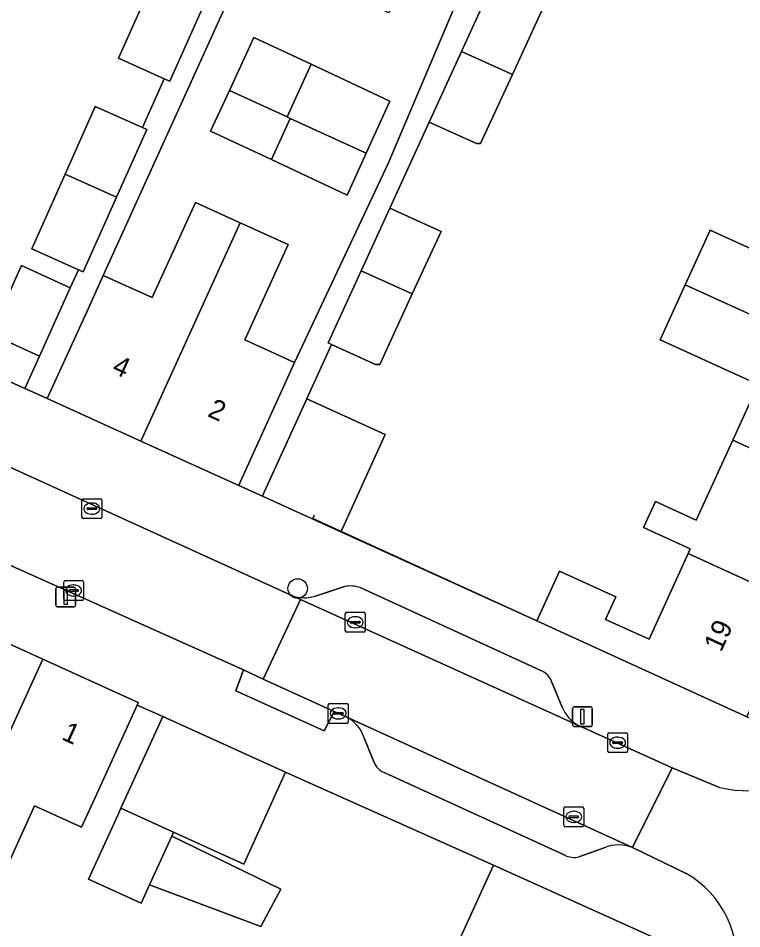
# Model space of a CAD drawing. Extents: x 161838 to 162344, y 381620 to 382160.
# Drawn here: x 162108.87 to 162145.23, y 381710.53 to 381756.3 of the extents above; entities that cross this region are included whole.
import ezdxf

# ---------------------------------------------------------------- set-up
doc = ezdxf.new("R2010")
doc.units = 0
for name, color, linetype in [('IMGEO_Boom', 7, 'Continuous'), ('IMGEO_Erf', 7, 'Continuous'), ('IMGEO_Kolk', 7, 'Continuous'), ('IMGEO_Lichtmast', 7, 'Continuous'), ('IMGEO_Muur', 7, 'Continuous'), ('IMGEO_Pand', 7, 'Continuous'), ('IMGEO_Pand_nummerreeks', 7, 'Continuous'), ('IMGEO_Parkeervlak_open', 7, 'Continuous'), ('IMGEO_Rijbaan_lokaal_open', 7, 'Continuous'), ('IMGEO_Voetpad_open', 7, 'Continuous')]:
    doc.layers.add(name, color=color, linetype=linetype)

msp = doc.modelspace()

# ---------------------------------------------------------------- linework, layer by layer
at = {"layer": 'IMGEO_Boom'}
msp.add_circle((162122.912, 381727.637), 0.489, dxfattribs=at)
at = {"layer": 'IMGEO_Erf'}
for points in [[(162094.462, 381744.361), (162109.199, 381737.693), (162109.937, 381739.317), (162107.478, 381740.434), (162109.029, 381743.87), (162111.487, 381742.753), (162111.903, 381743.659), (162109.549, 381744.71), (162111.227, 381748.467), (162112.742, 381751.86), (162115.113, 381750.802), (162116.21, 381753.261), (162113.902, 381754.292), (162115.58, 381758.049), (162117.095, 381761.442), (162119.401, 381760.413), (162120.584, 381763.066), (162118.111, 381764.199), (162119.612, 381767.472), (162119.687, 381767.636), (162117.321, 381768.718), (162119.551, 381773.591), (162104.902, 381780.293)], [(162135.187, 381756.685), (162133.706, 381753.472), (162132.105, 381750), (162131.895, 381750), (162129.52, 381751.082), (162127.539, 381746.757), (162130.115, 381745.582), (162128.667, 381742.44), (162127.033, 381738.897), (162126.823, 381738.897), (162124.609, 381739.906), (162123.489, 381737.446), (162123.366, 381737.176), (162127.307, 381735.385), (162125.559, 381731.538), (162125.24, 381730.836), (162125.078, 381730.479), (162134.933, 381726.013), (162136.075, 381728.515), (162138.903, 381727.225), (162138.383, 381726.082), (162140.569, 381725.085), (162142.533, 381729.392), (162142.638, 381729.623), (162140.29, 381730.694), (162140.887, 381732.002), (162142.937, 381731.066), (162144.775, 381735.096), (162146.048, 381737.887), (162141.124, 381740.133), (162142.389, 381742.908), (162143.638, 381745.647), (162148.57, 381743.398)], [(162131, 381709.87), (162132.746, 381713.736), (162123.45, 381717.876), (162122.299, 381718.4), (162120.198, 381713.786), (162116.674, 381715.392), (162116.58, 381715.187), (162122.071, 381712.514), (162121.067, 381710.646), (162115.466, 381712.742), (162115.047, 381711.821), (162112.406, 381713.024), (162113.885, 381716.271), (162114.033, 381716.595), (162116.134, 381721.209), (162114.846, 381721.774), (162112.829, 381717.348), (162112.052, 381715.642), (162109.694, 381716.716), (162107.482, 381711.859)]]:
    msp.add_lwpolyline(points, dxfattribs=at)
for points in [[(162125.234, 381757.602), (162122.862, 381758.683), (162125.159, 381763.719), (162122.868, 381764.764), (162119.303, 381756.947), (162113.142, 381743.376), (162115.598, 381742.26), (162117.771, 381747.043), (162120.024, 381746.019), (162122.432, 381744.925), (162120.257, 381740.137), (162122.76, 381739), (162127.457, 381749.002), (162132.322, 381760.48), (162129.803, 381761.628), (162127.496, 381756.57)], [(162127.539, 381752.13), (162126.353, 381749.521), (162125.392, 381747.407), (162121.589, 381749.193), (162118.534, 381750.627), (162119.48, 381752.676), (162120.709, 381755.336), (162123.585, 381753.986)]]:
    msp.add_lwpolyline(points, close=True, dxfattribs=at)
at = {"layer": 'IMGEO_Kolk'}
for p, q in [((162112.07, 381731.224), (162112.07, 381732.076)), ((162112.145, 381732.15), (162112.997, 381732.15)), ((162113.071, 381732.076), (162113.071, 381731.224)), ((162112.329, 381731.644), (162112.329, 381731.656)), ((162112.372, 381731.693), (162112.77, 381731.693)), ((162112.558, 381731.93), (162112.583, 381731.93)), ((162112.813, 381731.656), (162112.813, 381731.644)), ((162112.767, 381731.607), (162112.369, 381731.607)), ((162112.581, 381731.37), (162112.556, 381731.37)), ((162112.997, 381731.15), (162112.145, 381731.15)), ((162111.153, 381727.109), (162111.153, 381727.961)), ((162111.228, 381728.035), (162112.08, 381728.035)), ((162112.154, 381727.961), (162112.154, 381727.109)), ((162111.412, 381727.529), (162111.412, 381727.541)), ((162111.85, 381727.492), (162111.452, 381727.492)), ((162111.455, 381727.578), (162111.853, 381727.578)), ((162111.641, 381727.815), (162111.666, 381727.815)), ((162111.896, 381727.541), (162111.896, 381727.529)), ((162112.08, 381727.035), (162111.228, 381727.035)), ((162111.664, 381727.255), (162111.639, 381727.255)), ((162125.305, 381725.513), (162125.305, 381726.365)), ((162125.38, 381726.439), (162126.232, 381726.439)), ((162125.793, 381726.219), (162125.818, 381726.219)), ((162126.306, 381726.365), (162126.306, 381725.513)), ((162125.564, 381725.933), (162125.564, 381725.945)), ((162126.002, 381725.896), (162125.604, 381725.896)), ((162125.607, 381725.982), (162126.005, 381725.982)), ((162125.816, 381725.659), (162125.791, 381725.659)), ((162126.048, 381725.945), (162126.048, 381725.933)), ((162126.232, 381725.439), (162125.38, 381725.439)), ((162124.451, 381720.931), (162124.451, 381721.783)), ((162124.526, 381721.857), (162125.378, 381721.857)), ((162124.939, 381721.637), (162124.964, 381721.637)), ((162125.452, 381721.783), (162125.452, 381720.931)), ((162124.71, 381721.351), (162124.71, 381721.363)), ((162125.148, 381721.314), (162124.75, 381721.314)), ((162124.753, 381721.4), (162125.151, 381721.4)), ((162125.194, 381721.363), (162125.194, 381721.351)), ((162125.378, 381720.857), (162124.526, 381720.857)), ((162124.962, 381721.077), (162124.937, 381721.077)), ((162138.491, 381719.458), (162138.491, 381720.31)), ((162138.566, 381720.384), (162139.418, 381720.384)), ((162139.492, 381720.31), (162139.492, 381719.458)), ((162138.75, 381719.878), (162138.75, 381719.89)), ((162139.188, 381719.841), (162138.79, 381719.841)), ((162138.793, 381719.927), (162139.191, 381719.927)), ((162138.979, 381720.164), (162139.004, 381720.164)), ((162139.234, 381719.89), (162139.234, 381719.878)), ((162139.418, 381719.384), (162138.566, 381719.384)), ((162139.002, 381719.604), (162138.977, 381719.604)), ((162136.286, 381715.731), (162136.286, 381716.583)), ((162136.361, 381716.657), (162137.213, 381716.657)), ((162137.287, 381716.583), (162137.287, 381715.731)), ((162136.545, 381716.151), (162136.545, 381716.163)), ((162136.983, 381716.114), (162136.585, 381716.114)), ((162136.588, 381716.2), (162136.986, 381716.2)), ((162136.774, 381716.437), (162136.799, 381716.437)), ((162137.029, 381716.163), (162137.029, 381716.151)), ((162137.213, 381715.657), (162136.361, 381715.657)), ((162136.797, 381715.877), (162136.772, 381715.877))]:
    msp.add_line(p, q, dxfattribs=at)
for points in [[(162112.07, 381731.224), (162112.07, 381732.076)], [(162112.145, 381732.15), (162112.997, 381732.15)], [(162113.071, 381732.076), (162113.071, 381731.224)], [(162112.997, 381731.15), (162112.145, 381731.15)], [(162111.153, 381727.109), (162111.153, 381727.961)], [(162111.228, 381728.035), (162112.08, 381728.035)], [(162112.154, 381727.961), (162112.154, 381727.109)], [(162112.08, 381727.035), (162111.228, 381727.035)], [(162125.305, 381725.513), (162125.305, 381726.365)], [(162125.38, 381726.439), (162126.232, 381726.439)], [(162126.306, 381726.365), (162126.306, 381725.513)], [(162126.232, 381725.439), (162125.38, 381725.439)], [(162124.451, 381720.931), (162124.451, 381721.783)], [(162124.526, 381721.857), (162125.378, 381721.857)], [(162125.452, 381721.783), (162125.452, 381720.931)], [(162125.378, 381720.857), (162124.526, 381720.857)], [(162138.491, 381719.458), (162138.491, 381720.31)], [(162138.566, 381720.384), (162139.418, 381720.384)], [(162139.492, 381720.31), (162139.492, 381719.458)], [(162139.418, 381719.384), (162138.566, 381719.384)], [(162136.286, 381715.731), (162136.286, 381716.583)], [(162136.361, 381716.657), (162137.213, 381716.657)], [(162137.287, 381716.583), (162137.287, 381715.731)], [(162137.213, 381715.657), (162136.361, 381715.657)]]:
    msp.add_lwpolyline(points, dxfattribs=at)
for centre, radius, start, end in [((162112.147, 381732.074), 0.0765, 91.552, 178.448), ((162112.147, 381732.074), 0.0765, 91.552, 178.448), ((162112.995, 381732.074), 0.0765, 1.552, 88.448), ((162112.995, 381732.074), 0.0765, 1.552, 88.448), ((162112.369, 381731.653), 0.0403, 85.8775, 175.7526), ((162112.366, 381731.643), 0.0366, 178.938, 274.7102), ((162112.77, 381731.65), 0.043, 264.8664, 352.4533), ((162112.774, 381731.655), 0.0386, 1.7309, 96.639), ((162112.147, 381731.226), 0.0765, 181.552, 268.448), ((162112.147, 381731.226), 0.0765, 181.552, 268.448), ((162112.995, 381731.226), 0.0765, 271.552, 358.448), ((162112.995, 381731.226), 0.0765, 271.552, 358.448), ((162111.23, 381727.959), 0.0765, 91.552, 178.448), ((162111.23, 381727.959), 0.0765, 91.552, 178.448), ((162112.078, 381727.959), 0.0765, 1.552, 88.448), ((162112.078, 381727.959), 0.0765, 1.552, 88.448), ((162111.452, 381727.538), 0.0403, 85.8775, 175.7526), ((162111.449, 381727.528), 0.0366, 178.938, 274.7102), ((162111.853, 381727.535), 0.043, 264.8664, 352.4533), ((162111.857, 381727.54), 0.0386, 1.7309, 96.639), ((162111.23, 381727.111), 0.0765, 181.552, 268.448), ((162111.23, 381727.111), 0.0765, 181.552, 268.448), ((162112.078, 381727.111), 0.0765, 271.552, 358.448), ((162112.078, 381727.111), 0.0765, 271.552, 358.448), ((162125.382, 381726.363), 0.0765, 91.552, 178.448), ((162125.382, 381726.363), 0.0765, 91.552, 178.448), ((162126.23, 381726.363), 0.0765, 1.552, 88.448), ((162126.23, 381726.363), 0.0765, 1.552, 88.448), ((162125.604, 381725.942), 0.0403, 85.8775, 175.7526), ((162125.601, 381725.932), 0.0366, 178.938, 274.7102), ((162126.005, 381725.939), 0.043, 264.8664, 352.4533), ((162126.009, 381725.944), 0.0386, 1.7309, 96.639), ((162125.382, 381725.515), 0.0765, 181.552, 268.448), ((162125.382, 381725.515), 0.0765, 181.552, 268.448), ((162126.23, 381725.515), 0.0765, 271.552, 358.448), ((162126.23, 381725.515), 0.0765, 271.552, 358.448), ((162124.528, 381721.781), 0.0765, 91.552, 178.448), ((162124.528, 381721.781), 0.0765, 91.552, 178.448), ((162125.376, 381721.781), 0.0765, 1.552, 88.448), ((162125.376, 381721.781), 0.0765, 1.552, 88.448), ((162124.75, 381721.36), 0.0403, 85.8775, 175.7526), ((162124.747, 381721.35), 0.0366, 178.938, 274.7102), ((162125.151, 381721.357), 0.043, 264.8664, 352.4533), ((162125.155, 381721.362), 0.0386, 1.7309, 96.639), ((162124.528, 381720.933), 0.0765, 181.552, 268.448), ((162124.528, 381720.933), 0.0765, 181.552, 268.448), ((162125.376, 381720.933), 0.0765, 271.552, 358.448), ((162125.376, 381720.933), 0.0765, 271.552, 358.448), ((162138.568, 381720.308), 0.0765, 91.552, 178.448), ((162138.568, 381720.308), 0.0765, 91.552, 178.448), ((162139.416, 381720.308), 0.0765, 1.552, 88.448), ((162139.416, 381720.308), 0.0765, 1.552, 88.448), ((162138.79, 381719.887), 0.0403, 85.8775, 175.7526), ((162138.787, 381719.877), 0.0366, 178.938, 274.7102), ((162139.191, 381719.884), 0.043, 264.8664, 352.4533), ((162139.195, 381719.889), 0.0386, 1.7309, 96.639), ((162138.568, 381719.46), 0.0765, 181.552, 268.448), ((162138.568, 381719.46), 0.0765, 181.552, 268.448), ((162139.416, 381719.46), 0.0765, 271.552, 358.448), ((162139.416, 381719.46), 0.0765, 271.552, 358.448), ((162136.363, 381716.581), 0.0765, 91.552, 178.448), ((162136.363, 381716.581), 0.0765, 91.552, 178.448), ((162137.211, 381716.581), 0.0765, 1.552, 88.448), ((162137.211, 381716.581), 0.0765, 1.552, 88.448), ((162136.585, 381716.16), 0.0403, 85.8775, 175.7526), ((162136.582, 381716.15), 0.0366, 178.938, 274.7102), ((162136.986, 381716.157), 0.043, 264.8664, 352.4533), ((162136.99, 381716.162), 0.0386, 1.7309, 96.639), ((162136.363, 381715.733), 0.0765, 181.552, 268.448), ((162136.363, 381715.733), 0.0765, 181.552, 268.448), ((162137.211, 381715.733), 0.0765, 271.552, 358.448), ((162137.211, 381715.733), 0.0765, 271.552, 358.448)]:
    msp.add_arc(centre, radius, start, end, dxfattribs=at)
for centre, major_axis, ratio, start_param, end_param in [((162112.557, 381731.65), (-0.387, 0.002), 0.722429, 4.712389, 7.853982), ((162112.582, 381731.65), (-0.39, 0.002), 0.717154, 1.570796, 4.712389), ((162111.64, 381727.535), (-0.387, 0.002), 0.722429, 4.712389, 7.853982), ((162111.665, 381727.535), (-0.39, 0.002), 0.717154, 1.570796, 4.712389), ((162125.792, 381725.939), (-0.387, 0.002), 0.722429, 4.712389, 7.853982), ((162125.817, 381725.939), (-0.39, 0.002), 0.717154, 1.570796, 4.712389), ((162124.938, 381721.357), (-0.387, 0.002), 0.722429, 4.712389, 7.853982), ((162124.963, 381721.357), (-0.39, 0.002), 0.717154, 1.570796, 4.712389), ((162138.978, 381719.884), (-0.387, 0.002), 0.722429, 4.712389, 7.853982), ((162139.003, 381719.884), (-0.39, 0.002), 0.717154, 1.570796, 4.712389), ((162136.773, 381716.157), (-0.387, 0.002), 0.722429, 4.712389, 7.853982), ((162136.798, 381716.157), (-0.39, 0.002), 0.717154, 1.570796, 4.712389)]:
    msp.add_ellipse(centre, major_axis=major_axis, ratio=ratio, start_param=start_param, end_param=end_param, dxfattribs=at)
at = {"layer": 'IMGEO_Lichtmast'}
for p, q in [((162110.757, 381726.807), (162110.757, 381727.607)), ((162110.757, 381727.607), (162110.757, 381726.807)), ((162110.857, 381727.707), (162111.647, 381727.707)), ((162111.647, 381727.707), (162110.857, 381727.707)), ((162111.747, 381727.607), (162111.747, 381726.807)), ((162111.747, 381726.807), (162111.747, 381727.607)), ((162111.647, 381726.707), (162110.857, 381726.707)), ((162110.857, 381726.707), (162111.647, 381726.707)), ((162136.729, 381720.794), (162136.729, 381721.594)), ((162136.729, 381721.594), (162136.729, 381720.794)), ((162136.829, 381721.694), (162137.619, 381721.694)), ((162137.619, 381721.694), (162136.829, 381721.694)), ((162137.719, 381721.594), (162137.719, 381720.794)), ((162137.719, 381720.794), (162137.719, 381721.594)), ((162137.619, 381720.694), (162136.829, 381720.694)), ((162136.829, 381720.694), (162137.619, 381720.694))]:
    msp.add_line(p, q, dxfattribs=at)
for points in [[(162111.177, 381727.582), (162111.327, 381727.582), (162111.327, 381726.832), (162111.177, 381726.832), (162111.177, 381727.582)], [(162137.149, 381721.569), (162137.299, 381721.569), (162137.299, 381720.819), (162137.149, 381720.819), (162137.149, 381721.569)]]:
    msp.add_lwpolyline(points, dxfattribs=at)
for centre, start, end in [((162110.857, 381727.607), 90, 180), ((162110.857, 381727.607), 90, 180), ((162111.647, 381727.607), 0, 90), ((162111.647, 381727.607), 360, 90), ((162110.857, 381726.807), 180, 270), ((162110.857, 381726.807), 180, 270), ((162111.647, 381726.807), 270, 0), ((162111.647, 381726.807), 270, 0), ((162136.829, 381721.594), 90, 180), ((162136.829, 381721.594), 90, 180), ((162137.619, 381721.594), 0, 90), ((162137.619, 381721.594), 360, 90), ((162136.829, 381720.794), 180, 270), ((162136.829, 381720.794), 180, 270), ((162137.619, 381720.794), 270, 0), ((162137.619, 381720.794), 270, 0)]:
    msp.add_arc(centre, 0.1, start, end, dxfattribs=at)
at = {"layer": 'IMGEO_Muur'}
for points in [[(162094.462, 381744.361), (162109.441, 381737.584)], [(162134.933, 381726.013), (162123.679, 381731.147), (162123.762, 381731.335)], [(162132.746, 381713.736), (162123.45, 381717.876)]]:
    msp.add_lwpolyline(points, dxfattribs=at)
at = {"layer": 'IMGEO_Pand'}
for points in [[(162118.167, 381756.895), (162115.58, 381758.049), (162113.902, 381754.292), (162116.21, 381753.261), (162116.488, 381753.137)], [(162133.706, 381753.472), (162135.187, 381756.685), (162132.611, 381757.86), (162131.138, 381754.629)], [(162123.585, 381753.986), (162120.709, 381755.336), (162119.48, 381752.676), (162122.378, 381751.34)], [(162133.706, 381753.472), (162131.138, 381754.629), (162129.52, 381751.082), (162131.895, 381750), (162132.105, 381750)], [(162126.353, 381749.521), (162127.539, 381752.13), (162123.585, 381753.986), (162122.378, 381751.34), (162122.532, 381751.269)], [(162122.532, 381751.269), (162122.378, 381751.34), (162119.48, 381752.676), (162118.534, 381750.627), (162121.589, 381749.193)], [(162115.329, 381750.706), (162115.113, 381750.802), (162112.742, 381751.86), (162111.227, 381748.467), (162113.814, 381747.313)], [(162126.353, 381749.521), (162122.532, 381751.269), (162121.589, 381749.193), (162125.392, 381747.407)], [(162113.814, 381747.313), (162111.227, 381748.467), (162109.549, 381744.71), (162111.903, 381743.659), (162112.135, 381743.555)], [(162115.037, 381735.042), (162120.024, 381746.019), (162117.771, 381747.043), (162115.598, 381742.26), (162113.142, 381743.376), (162112.397, 381741.735), (162110.328, 381737.182)], [(162128.667, 381742.44), (162130.115, 381745.582), (162127.539, 381746.757), (162126.103, 381743.609)], [(162115.037, 381735.042), (162119.947, 381732.811), (162120.04, 381733.016), (162122.016, 381737.363), (162122.76, 381739), (162120.257, 381740.137), (162122.432, 381744.925), (162120.024, 381746.019)], [(162142.389, 381742.908), (162154.329, 381737.465), (162156.68, 381742.62), (162156.106, 381742.882), (162156.294, 381743.294), (162149.847, 381746.199), (162148.57, 381743.398), (162143.638, 381745.647)], [(162109.937, 381739.317), (162111.487, 381742.753), (162109.029, 381743.87), (162107.478, 381740.434)], [(162128.667, 381742.44), (162126.103, 381743.609), (162124.448, 381739.979), (162124.609, 381739.906), (162126.823, 381738.897), (162127.033, 381738.897)], [(162151.197, 381732.168), (162151.435, 381732.691), (162152.028, 381732.42), (162154.329, 381737.465), (162142.389, 381742.908), (162141.124, 381740.133), (162146.048, 381737.887), (162144.775, 381735.096)], [(162123.366, 381737.176), (162121.233, 381732.484), (162121.136, 381732.271), (162125.078, 381730.479), (162125.24, 381730.836), (162125.559, 381731.538), (162127.307, 381735.385)], [(162151.197, 381732.168), (162144.775, 381735.096), (162142.937, 381731.066), (162140.887, 381732.002), (162140.29, 381730.694), (162142.638, 381729.623), (162142.533, 381729.392), (162148.657, 381726.6)], [(162148.657, 381726.6), (162142.533, 381729.392), (162140.569, 381725.085), (162138.383, 381726.082), (162138.903, 381727.225), (162136.075, 381728.515), (162134.933, 381726.013), (162145.491, 381721.183), (162146.44, 381723.262), (162147.015, 381723)], [(162105.035, 381712.973), (162110.102, 381724.084), (162105.307, 381726.268), (162103.234, 381721.718), (162102.44, 381719.975), (162104.938, 381718.838), (162102.742, 381714.018)], [(162105.035, 381712.973), (162107.482, 381711.859), (162109.694, 381716.716), (162112.052, 381715.642), (162112.829, 381717.348), (162114.846, 381721.774), (162114.902, 381721.897), (162110.102, 381724.084)], [(162122.299, 381718.4), (162116.134, 381721.209), (162114.033, 381716.595), (162116.674, 381715.392), (162120.198, 381713.786)], [(162116.58, 381715.187), (162116.674, 381715.392), (162114.033, 381716.595), (162113.885, 381716.271), (162112.406, 381713.024), (162115.047, 381711.821), (162115.466, 381712.742)], [(162116.58, 381715.187), (162115.466, 381712.742), (162121.067, 381710.646), (162122.071, 381712.514)], [(162132.746, 381713.736), (162131, 381709.87), (162130.573, 381708.924), (162130.463, 381708.68), (162139.358, 381704.662), (162139.558, 381704.572), (162141.842, 381709.627)]]:
    msp.add_lwpolyline(points, close=True, dxfattribs=at)
at = {"layer": 'IMGEO_Parkeervlak_open'}
for points in [[(162125.26, 381727.733), (162123.75, 381727.241)], [(162135.135, 381723.508), (162126.053, 381727.681)], [(162122.654, 381727.261), (162123.059, 381727.078), (162136.993, 381720.77)], [(162136.208, 381721.672), (162135.665, 381722.965)], [(162139.744, 381714.61), (162125.376, 381721.164)], [(162126.235, 381720.163), (162126.734, 381718.92)], [(162127.252, 381718.378), (162136.296, 381714.252)], [(162137.088, 381714.157), (162138.318, 381714.599)]]:
    msp.add_lwpolyline(points, dxfattribs=at)
for centre, radius, start, end in [((162125.563, 381726.278), 1.486, 70.738, 101.7585), ((162123.236, 381729.137), 1.965, 252.7545, 285.1546), ((162134.804, 381722.655), 0.915, 19.8027, 68.809), ((162137.907, 381722.358), 1.832, 201.9897, 240.0756), ((162124.638, 381719.662), 1.674, 17.4279, 63.8407), ((162127.701, 381719.325), 1.048, 202.752, 244.6539), ((162139.044, 381712.892), 1.855, 67.8377, 113.0463), ((162136.805, 381715.15), 1.033, 240.4415, 285.8787)]:
    msp.add_arc(centre, radius, start, end, dxfattribs=at)
at = {"layer": 'IMGEO_Rijbaan_lokaal_open'}
for points in [[(162101.956, 381731.713), (162120.195, 381723.542), (162121.174, 381723.086), (162123.059, 381727.078), (162122.654, 381727.261), (162103.87, 381735.811)], [(162125.376, 381721.164), (162139.744, 381714.61), (162141.73, 381718.622), (162136.993, 381720.77), (162123.059, 381727.078), (162121.174, 381723.086), (162124.741, 381721.45)]]:
    msp.add_lwpolyline(points, close=True, dxfattribs=at)
msp.add_lwpolyline([(162144.103, 381717.64), (162141.73, 381718.622), (162139.744, 381714.61), (162142.428, 381713.317)], dxfattribs=at)
for centre, radius, start, end in [((162145.563, 381723.765), 6.297, 256.5959, 313.0128), ((162139.982, 381708.972), 4.986, 349.8837, 60.6274)]:
    msp.add_arc(centre, radius, start, end, dxfattribs=at)
at = {"layer": 'IMGEO_Voetpad_open'}
for points in [[(162129.52, 381751.082), (162131.138, 381754.629), (162132.611, 381757.86), (162136.277, 381765.957), (162135.827, 381766.161), (162135.069, 381766.503), (162132.994, 381761.954), (162132.322, 381760.48), (162127.457, 381749.002), (162122.76, 381739), (162122.016, 381737.363), (162120.04, 381733.016), (162119.947, 381732.811), (162121.136, 381732.271), (162121.233, 381732.484), (162123.366, 381737.176), (162123.489, 381737.446), (162124.609, 381739.906), (162124.448, 381739.979), (162126.103, 381743.609), (162127.539, 381746.757)], [(162124.741, 381721.45), (162121.174, 381723.086), (162120.195, 381723.542), (162119.809, 381722.495), (162124.241, 381720.486)]]:
    msp.add_lwpolyline(points, close=True, dxfattribs=at)
for points in [[(162118.167, 381756.895), (162116.488, 381753.137), (162116.21, 381753.261), (162115.113, 381750.802), (162115.329, 381750.706), (162113.814, 381747.313), (162112.135, 381743.555), (162111.903, 381743.659), (162111.487, 381742.753), (162109.937, 381739.317), (162109.199, 381737.693), (162109.441, 381737.584), (162110.328, 381737.182), (162112.397, 381741.735), (162113.142, 381743.376), (162119.303, 381756.947)], [(162115.037, 381735.042), (162110.328, 381737.182), (162109.441, 381737.584), (162109.199, 381737.693), (162094.462, 381744.361), (162085.784, 381748.23), (162086.038, 381748.793), (162083.788, 381749.81), (162080.79, 381751.291), (162080.545, 381750.749), (162079.471, 381748.488), (162082.026, 381747.073), (162081.506, 381746.115), (162084.495, 381744.526)], [(162075.442, 381738.951), (162078.267, 381737.638), (162080.663, 381736.548), (162080.942, 381737.161), (162085.927, 381734.893), (162090.772, 381732.737), (162104.139, 381726.788), (162104.332, 381726.702), (162105.307, 381726.268), (162110.102, 381724.084), (162114.902, 381721.897), (162114.846, 381721.774), (162116.134, 381721.209), (162122.299, 381718.4), (162123.45, 381717.876), (162132.746, 381713.736), (162141.842, 381709.627), (162144.891, 381708.096)], [(162103.292, 381736.059), (162103.87, 381735.811), (162122.654, 381727.261)], [(162149.858, 381719.161), (162145.491, 381721.183), (162134.933, 381726.013), (162125.078, 381730.479), (162121.136, 381732.271), (162119.947, 381732.811), (162115.037, 381735.042)], [(162125.376, 381721.164), (162124.741, 381721.45), (162124.241, 381720.486), (162119.809, 381722.495), (162120.195, 381723.542), (162101.956, 381731.713)], [(162123.75, 381727.241), (162125.26, 381727.733)], [(162126.053, 381727.681), (162135.135, 381723.508)], [(162135.665, 381722.965), (162136.208, 381721.672)], [(162136.993, 381720.77), (162141.73, 381718.622), (162144.103, 381717.64)], [(162126.734, 381718.92), (162126.235, 381720.163)], [(162136.296, 381714.252), (162127.252, 381718.378)], [(162138.318, 381714.599), (162137.088, 381714.157)], [(162142.428, 381713.317), (162139.744, 381714.61)]]:
    msp.add_lwpolyline(points, dxfattribs=at)
for centre, radius, start, end in [((162125.563, 381726.278), 1.486, 70.738, 101.7585), ((162123.236, 381729.137), 1.965, 252.7545, 285.1546), ((162134.804, 381722.655), 0.915, 19.8027, 68.809), ((162137.907, 381722.358), 1.832, 201.9897, 240.0756), ((162124.638, 381719.662), 1.674, 17.4279, 63.8407), ((162127.701, 381719.325), 1.048, 202.752, 244.6539), ((162145.563, 381723.765), 6.297, 256.5959, 313.0128), ((162139.044, 381712.892), 1.855, 67.8377, 113.0463), ((162136.805, 381715.15), 1.033, 240.4415, 285.8787), ((162139.982, 381708.972), 4.986, 349.8837, 60.6274)]:
    msp.add_arc(centre, radius, start, end, dxfattribs=at)

# ---------------------------------------------------------------- texts
at = {"layer": 'IMGEO_Pand_nummerreeks'}
for s, rotation, p in [('4', 335.5623, (162113.525, 381738.497)), ('2', 335.5623, (162118.333, 381736.313)), ('19', 65.4648, (162144.19, 381724.4)), ('1', 335.5084, (162110.997, 381720.072))]:
    msp.add_text(s, height=1, rotation=rotation, dxfattribs=at).set_placement(p)

doc.saveas('drawing.dxf')
